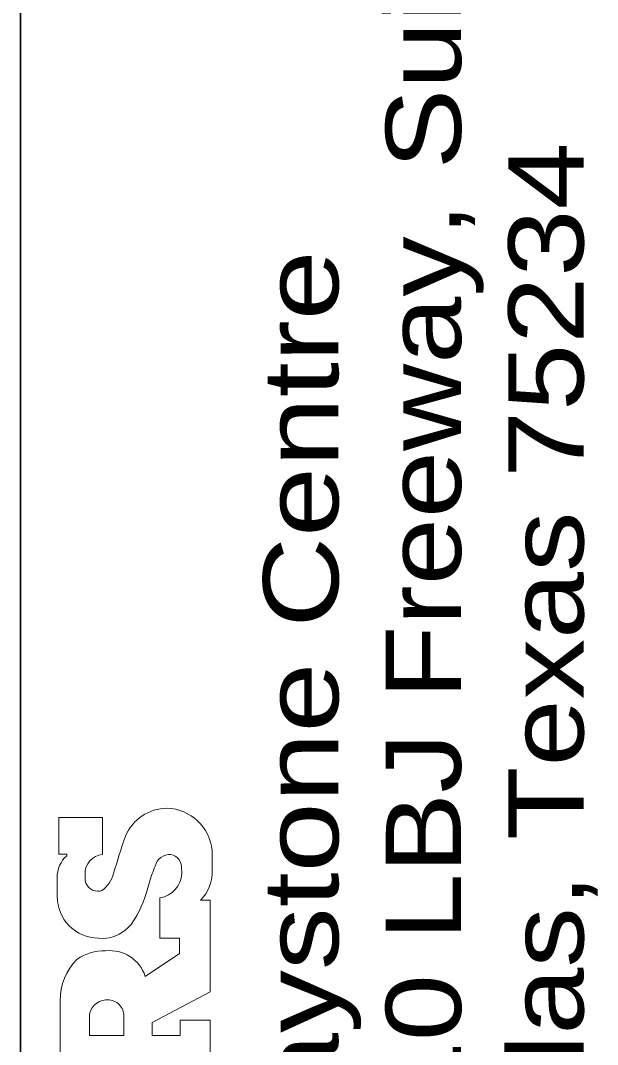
# Model space of a CAD drawing. Extents: x 2363323 to 2367082, y 6956018 to 6980837.
# Drawn here: x 2366602.4 to 2366703.8, y 6957348.9 to 6957528.9 of the extents above; entities that cross this region are included whole.
import ezdxf

# ---------------------------------------------------------------- set-up
doc = ezdxf.new("R2010")
doc.units = 0
doc.header["$LTSCALE"] = 4.1
doc.layers.add('62', color=7, linetype='Continuous', lineweight=13)
doc.layers.add('63', color=7, linetype='Continuous', lineweight=13)

msp = doc.modelspace()

# ---------------------------------------------------------------- linework, layer by layer
at = {"layer": '62', "lineweight": 35}
msp.add_line((2366602.353, 6957951.933), (2366602.354, 6957300.911), dxfattribs=at)
at = {"layer": '62'}
for p, q in [((2366636.023, 6957382.973), (2366636.023, 6957379.639)), ((2366630.694, 6957378.932), (2366630.654, 6957380.133)), ((2366608.799, 6957374.906), (2366608.799, 6957378.241)), ((2366613.725, 6957378.82), (2366613.725, 6957378.134)), ((2366614.502, 6957350.491), (2366614.502, 6957354.256))]:
    msp.add_line(p, q, dxfattribs=at)
for points in [[(2366610.487, 6957382.087), (2366610.487, 6957382.328), (2366609.122, 6957382.328), (2366609.122, 6957388.781), (2366616.762, 6957388.781), (2366616.762, 6957382.328)], [(2366624.273, 6957360.875), (2366630.32, 6957364.904), (2366630.32, 6957367.593), (2366626.876, 6957367.593), (2366626.876, 6957374.691)], [(2366633.978, 6957374.261), (2366635.7, 6957374.261), (2366635.7, 6957358.128), (2366625.477, 6957352.75), (2366625.477, 6957350.491), (2366630.427, 6957350.491), (2366630.427, 6957353.18), (2366635.7, 6957353.18), (2366635.7, 6957339.306), (2366630.32, 6957339.306), (2366630.32, 6957341.779), (2366614.502, 6957341.779), (2366614.502, 6957337.154), (2366626.338, 6957337.154)], [(2366626.338, 6957329.948), (2366614.394, 6957329.948), (2366614.394, 6957327.582), (2366609.337, 6957327.582), (2366609.337, 6957356.622)], [(2366620.528, 6957353.61), (2366620.528, 6957350.491), (2366614.502, 6957350.491)]]:
    msp.add_lwpolyline(points, dxfattribs=at)
for centre, radius, start, end in [((2366628.197, 6957382.424), 8.011, 90.4748, 157.35647), ((2366627.84, 6957382.223), 8.217, 5.23994, 87.97211), ((2366787.278, 6957328.558), 175.947, 161.11463, 163.35109), ((2366613.996, 6957378.253), 5.197, 132.47521, 180.13887), ((2366617.05, 6957379.009), 3.331, 94.97622, 183.26328), ((2366628.628, 6957379.619), 2.67, 86.42761, 166.58817), ((2366628.408, 6957380.071), 2.246, 1.56527, 80.09036), ((2366651.51, 6957369.415), 27.683, 156.98519, 163.48674), ((2366615.89, 6957378.029), 2.168, 177.22466, 270.15025), ((2366613.479, 6957380.285), 5.391, 306.33025, 345.86761), ((2366626.214, 6957379.126), 4.484, 278.49107, 357.52171), ((2366629.231, 6957379.143), 6.809, 314.19553, 4.1738), ((2366603.065, 6957382.371), 22.488, 329.02736, 346.92656), ((2366616.169, 6957374.948), 7.37, 180.32724, 269.1529), ((2366616.119, 6957377.511), 1.665, 262.3102, 289.43935), ((2366616.681, 6957374.114), 6.564, 264.56461, 329.65547), ((2366619.529, 6957356.707), 10.193, 135.41811, 180.47644), ((2366617.026, 6957357.061), 8.298, 87.96198, 124.96984), ((2366618.087, 6957358.909), 6.491, 17.63424, 96.78306), ((2366617.54, 6957353.655), 3.097, 81.97357, 168.82266), ((2366617.709, 6957353.901), 2.833, 354.11318, 84.67155)]:
    msp.add_arc(centre, radius, start, end, dxfattribs=at)
at = {"layer": '63', "lineweight": 35}
msp.add_line((2366602.353, 6957951.933), (2366602.354, 6957300.911), dxfattribs=at)

# ---------------------------------------------------------------- texts
at = {"layer": '62'}
for s, width, p in [('3010 LBJ Freeway, Suite 1300', 1.2, (2366679.786, 6957314.081)), ('Dallas, Texas 75234', 1.2, (2366701.333, 6957314.081)), ('Graystone Centre', 1.25, (2366658.238, 6957314.081))]:
    msp.add_text(s, height=13.22, rotation=90, dxfattribs=dict(at, width=width)).set_placement(p)

doc.saveas('drawing.dxf')
